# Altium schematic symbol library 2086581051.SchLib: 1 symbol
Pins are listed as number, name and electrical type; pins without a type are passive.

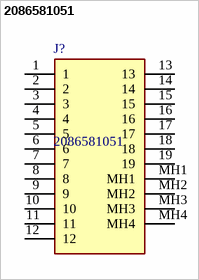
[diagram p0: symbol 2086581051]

## 2086581051
designator J?
1.0 HDMI R/A HEADER ASSy (I/M type); Manufacturer_Name: Molex; Geometry.Height: 6.44mm
footprint 2086581051
pins: 1, 2, 3, 4, 5, 6, 7, 8, 9, 10, 11, 12, 13, 14, 15, 16, 17, 18, 19, MH1, MH2, MH3, MH4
